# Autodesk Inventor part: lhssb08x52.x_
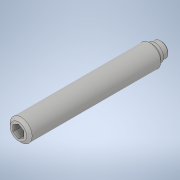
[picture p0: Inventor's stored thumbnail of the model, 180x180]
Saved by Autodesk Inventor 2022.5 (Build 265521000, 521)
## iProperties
Created: 2021-02
Part Number: lhssb08x52.x_
Material: 一般
Document SubType Name: Modeling
Designer: ImaoCorp
Density: 1 g/cm^3
Appearance: 既定
Sending System: SOLIDWORKS 2019-2019304
MC: AMD64
MC_MODEL: Intel64 Family 6 Model 60 Stepping 3, GenuineIntel
OS: Windows_NT
FRU: Parasolid Version 31.0, build 290,  9- 1-2019
FORMAT: text
GUISE: transmit
KEY: lhssb08x52
FILE: lhssb08x52.x_t
DATE: Mon Feb 22 14:56:00 2021
Author: ImaoCorp
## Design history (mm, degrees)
feature "Base1"
node "ソリッド1"
